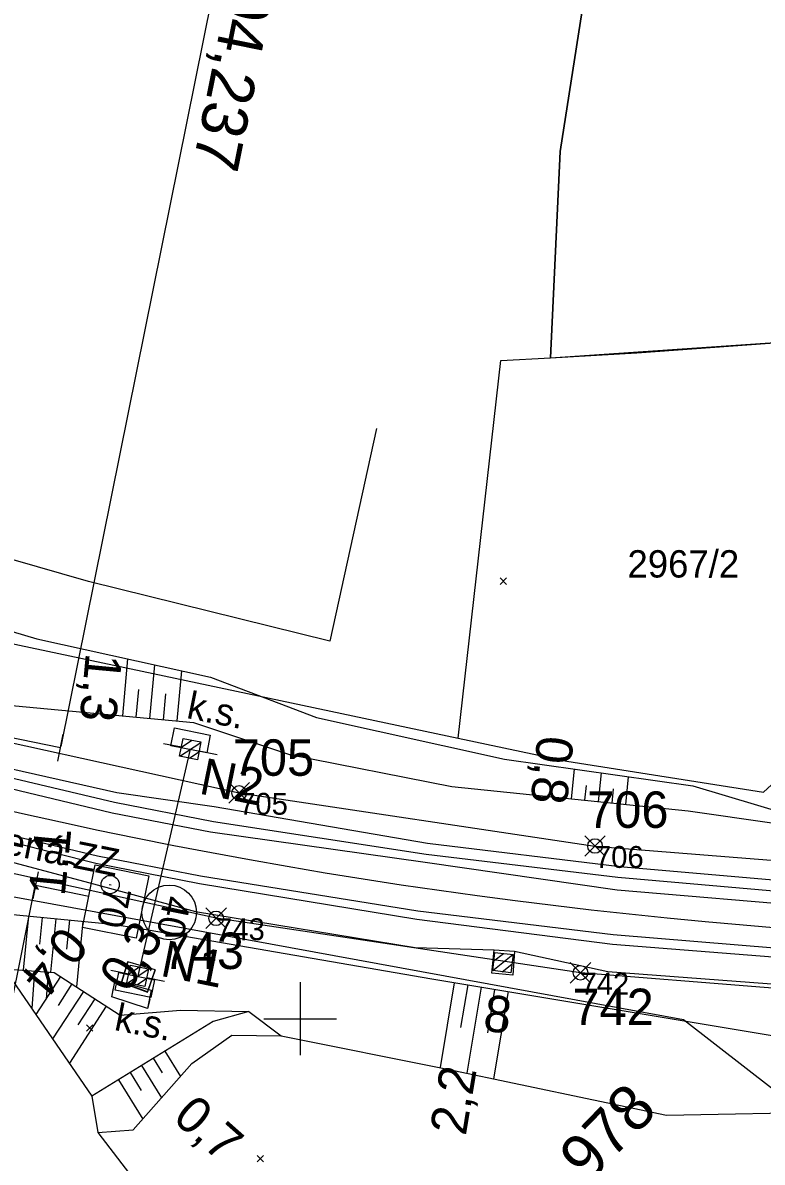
# Model space of a CAD drawing. Extents: x -800194 to -799078, y -1007177 to -1006597.
# Drawn here: x -799715.2 to -799674.6, y -1007007.9 to -1006945.3 of the extents above; entities that cross this region are included whole.
import ezdxf

# ---------------------------------------------------------------- set-up
doc = ezdxf.new("R2010")
doc.units = 0
for name, color, linetype in [('02_Osa_koleje', 7, 'Continuous'), ('Obvod stavby', 7, 'Continuous'), ('Ramove udaje', 7, 'Continuous'), ('Vrstva 11', 7, 'Continuous'), ('Vrstva 12', 7, 'Continuous'), ('Vrstva 17', 7, 'Continuous'), ('Vrstva 2', 7, 'Continuous'), ('Vrstva 23', 7, 'Continuous'), ('Vrstva 25', 7, 'Continuous'), ('Vrstva 4', 7, 'Continuous'), ('Vrstva 48', 7, 'Continuous'), ('Vrstva 49', 7, 'Continuous'), ('Vrstva 5', 7, 'Continuous'), ('Vrstva 50', 7, 'Continuous'), ('Vrstva 53', 7, 'Continuous'), ('Vrstva 55', 7, 'Continuous'), ('Vrstva 57', 7, 'Continuous'), ('Vrstva 60', 7, 'Continuous')]:
    doc.layers.add(name, color=color, linetype=linetype)

msp = doc.modelspace()

# ---------------------------------------------------------------- linework, layer by layer
at = {"layer": '02_Osa_koleje'}
msp.add_arc((-799651.022, -1006703.891), 292, 255.62486, 308.20516, dxfattribs=at)
at = {"layer": 'Obvod stavby'}
for p, q in [((-799703.915, -1006988.172), (-799702.784, -1006987.041)), ((-799703.915, -1006987.041), (-799702.784, -1006988.172)), ((-799684.371, -1006991.088), (-799683.24, -1006989.957)), ((-799684.371, -1006989.957), (-799683.24, -1006991.088)), ((-799705.185, -1006995.056), (-799704.054, -1006993.924)), ((-799705.185, -1006993.924), (-799704.054, -1006995.056)), ((-799685.167, -1006998.043), (-799684.036, -1006996.912)), ((-799685.167, -1006996.912), (-799684.036, -1006998.043))]:
    msp.add_line(p, q, dxfattribs=at)
msp.add_lwpolyline([(-799664.426, -1006999.087), (-799684.601, -1006997.477), (-799704.619, -1006994.49), (-799724.386, -1006990.14), (-799749.554, -1006982.491), (-799772.102, -1006973.528), (-799780.707, -1006969.551), (-799777.674, -1006963.242), (-799769.263, -1006967.129), (-799747.228, -1006975.889), (-799722.648, -1006983.359), (-799703.35, -1006987.606), (-799683.806, -1006990.523), (-799664.228, -1006992.091)], dxfattribs=at)
for centre in [(-799703.35, -1006987.606), (-799683.806, -1006990.523), (-799704.619, -1006994.49), (-799684.601, -1006997.477)]:
    msp.add_circle(centre, 0.4, dxfattribs=at)
at = {"layer": 'Ramove udaje'}
for p, q in [((-799700, -1006998), (-799700, -1007002)), ((-799702, -1007000), (-799700, -1007000)), ((-799700, -1007000), (-799698, -1007000))]:
    msp.add_line(p, q, dxfattribs=at)
at = {"layer": 'Vrstva 11'}
for p, q in [((-799706.526, -1006985.106), (-799707.506, -1006984.907)), ((-799706.602, -1006985.6), (-799705.452, -1006984.836)), ((-799706.525, -1006985.099), (-799705.943, -1006984.713)), ((-799706.036, -1006985.204), (-799708.923, -1006997.646)), ((-799706.082, -1006985.705), (-799705.557, -1006985.356)), ((-799705.546, -1006985.304), (-799704.566, -1006985.501)), ((-799689.419, -1006997.352), (-799688.31, -1006996.481)), ((-799689.355, -1006996.825), (-799688.836, -1006996.418)), ((-799709.413, -1006997.548), (-799710.393, -1006997.349)), ((-799709.489, -1006998.042), (-799708.339, -1006997.278)), ((-799709.412, -1006997.541), (-799708.83, -1006997.155)), ((-799688.896, -1006997.418), (-799688.37, -1006997.005)), ((-799708.969, -1006998.147), (-799708.444, -1006997.798)), ((-799708.433, -1006997.746), (-799707.453, -1006997.943))]:
    msp.add_line(p, q, dxfattribs=at)
for points in [[(-799706.427, -1006984.615), (-799705.447, -1006984.813), (-799705.645, -1006985.793), (-799706.625, -1006985.595)], [(-799689.3, -1006996.362), (-799688.307, -1006996.481), (-799688.426, -1006997.474), (-799689.419, -1006997.355)], [(-799709.314, -1006997.057), (-799708.334, -1006997.255), (-799708.532, -1006998.235), (-799709.512, -1006998.037)]]:
    msp.add_lwpolyline(points, close=True, dxfattribs=at)
at = {"layer": 'Vrstva 12'}
for p, q in [((-799709.809, -1006998.009), (-799709.806, -1006998.009)), ((-799708.388, -1006998.534), (-799708.385, -1006998.533))]:
    msp.add_line(p, q, dxfattribs=at)
for points in [[(-799689.347, -1006996.226), (-799688.222, -1006996.296), (-799688.323, -1006997.618), (-799689.475, -1006997.506), (-799689.347, -1006996.226)], [(-799707.958, -1006997.313), (-799708.385, -1006998.533), (-799709.809, -1006998.009), (-799709.473, -1006996.883)], [(-799707.958, -1006997.313), (-799709.473, -1006996.883), (-799709.806, -1006998.009), (-799708.388, -1006998.534), (-799707.958, -1006997.313)]]:
    msp.add_lwpolyline(points, dxfattribs=at)
at = {"layer": 'Vrstva 17'}
for points in [[(-799695.807, -1006967.611), (-799698.37, -1006979.283), (-799711.621, -1006976.014), (-799725.913, -1006971.918), (-799726.806, -1006975.491)], [(-799708.261, -1006998.95), (-799708.384, -1006999.431), (-799710.346, -1006998.801), (-799710.257, -1006998.331)]]:
    msp.add_lwpolyline(points, dxfattribs=at)
at = {"layer": 'Vrstva 23'}
msp.add_lwpolyline([(-799710.163, -1006997.878), (-799708.18, -1006998.442), (-799708.384, -1006999.431), (-799710.346, -1006998.801), (-799710.163, -1006997.878)], dxfattribs=at)
at = {"layer": 'Vrstva 25'}
for points in [[(-799707.094, -1006985.017), (-799706.896, -1006984.037), (-799704.936, -1006984.433), (-799705.134, -1006985.413), (-799707.094, -1006985.017)], [(-799708.002, -1006997.857), (-799708.2, -1006998.837), (-799710.16, -1006998.441), (-799709.962, -1006997.461), (-799708.002, -1006997.857)]]:
    msp.add_lwpolyline(points, dxfattribs=at)
at = {"layer": 'Vrstva 4'}
for points in [[(-799766.319, -1006970.565), (-799760.949, -1006972.542), (-799747.638, -1006977.46), (-799730.549, -1006982.982), (-799710.066, -1006987.578), (-799704.728, -1006988.346), (-799693.001, -1006990.373), (-799682.434, -1006991.64), (-799671.27, -1006992.619), (-799659.31, -1006993.026), (-799648.69, -1006993.125), (-799637.398, -1006992.704), (-799625.913, -1006992.175), (-799614.965, -1006990.831), (-799603.911, -1006989.312), (-799592.728, -1006987.172), (-799581.605, -1006984.547), (-799570.583, -1006981.598), (-799559.909, -1006978.216), (-799542.956, -1006972.25), (-799531.79, -1006967.658), (-799521.285, -1006962.191), (-799511.236, -1006957.129)], [(-799779.678, -1006964.304), (-799766.319, -1006970.565), (-799761.253, -1006973.176), (-799747.77, -1006978.421), (-799730.774, -1006983.8), (-799710.333, -1006988.709), (-799704.916, -1006989.741), (-799693.131, -1006991.407), (-799682.585, -1006992.929), (-799671.325, -1006993.879), (-799659.363, -1006994.45), (-799648.66, -1006994.501), (-799637.23, -1006994.127), (-799626.066, -1006993.335), (-799614.788, -1006992.17), (-799603.669, -1006990.506), (-799592.467, -1006988.452), (-799581.281, -1006985.916), (-799570.22, -1006982.998), (-799559.296, -1006979.606), (-799542.375, -1006973.485), (-799531.236, -1006968.774), (-799520.48, -1006963.762), (-799510.394, -1006958.536)], [(-799776.864, -1006969.085), (-799770.965, -1006971.646), (-799761.91, -1006975.649), (-799748.544, -1006980.777), (-799731.457, -1006986.215), (-799711.132, -1006991.054), (-799705.482, -1006992.16), (-799693.53, -1006994.084), (-799682.801, -1006995.384), (-799671.514, -1006996.319), (-799659.449, -1006996.851), (-799648.588, -1006996.949), (-799637.262, -1006996.573), (-799625.835, -1006995.773), (-799614.546, -1006994.586), (-799603.199, -1006992.945), (-799591.969, -1006990.857), (-799580.647, -1006988.335), (-799569.534, -1006985.311), (-799558.557, -1006981.947), (-799541.405, -1006975.739), (-799530.263, -1006971.071), (-799519.455, -1006966), (-799509.248, -1006960.724)], [(-799776.864, -1006969.085), (-799771.262, -1006971.982), (-799762.131, -1006976.093), (-799748.706, -1006981.286), (-799731.51, -1006986.353), (-799711.222, -1006991.459), (-799705.527, -1006992.587), (-799693.582, -1006994.543), (-799682.85, -1006995.904), (-799671.5, -1006996.805), (-799659.556, -1006997.356), (-799648.616, -1006997.341), (-799637.276, -1006997.071), (-799625.828, -1006996.297), (-799614.43, -1006995.109), (-799603.18, -1006993.475), (-799591.849, -1006991.264), (-799580.564, -1006988.698), (-799569.449, -1006985.746), (-799558.385, -1006982.386), (-799541.268, -1006976.227), (-799530.102, -1006971.505), (-799519.398, -1006966.36), (-799509.087, -1006961.127)], [(-799779.011, -1006963.023), (-799770.632, -1006967.944), (-799766.319, -1006970.565), (-799761.021, -1006972.82), (-799747.748, -1006977.966), (-799730.719, -1006983.271), (-799710.195, -1006988.108), (-799704.765, -1006989.181), (-799693.072, -1006990.965), (-799682.554, -1006992.238), (-799671.266, -1006993.222), (-799659.388, -1006993.765), (-799648.658, -1006993.824), (-799637.385, -1006993.531), (-799625.769, -1006992.728), (-799614.9, -1006991.542), (-799603.91, -1006989.963), (-799592.572, -1006987.892), (-799581.421, -1006985.419), (-799570.327, -1006982.332), (-799559.429, -1006979.066), (-799542.601, -1006973.013), (-799531.454, -1006968.25), (-799520.744, -1006963.214)], [(-799776.864, -1006969.085), (-799771.693, -1006972.522), (-799762.217, -1006976.394), (-799748.898, -1006981.647), (-799733.68, -1006986.66), (-799728.795, -1006987.945), (-799711.349, -1006992.599), (-799705.744, -1006994.116), (-799693.689, -1006996.09), (-799689.347, -1006996.226), (-799688.222, -1006996.296), (-799683.105, -1006997.407), (-799671.667, -1006998.275)]]:
    msp.add_lwpolyline(points, dxfattribs=at)
at = {"layer": 'Vrstva 48'}
for p, q in [((-799709.746, -1006983.382), (-799709.457, -1006980.257)), ((-799708.252, -1006983.521), (-799707.98, -1006980.58)), ((-799706.759, -1006983.659), (-799706.504, -1006980.903)), ((-799708.999, -1006983.452), (-799708.859, -1006981.935)), ((-799707.506, -1006983.59), (-799707.374, -1006982.166)), ((-799685.1, -1006987.935), (-799684.931, -1006986.304)), ((-799683.608, -1006988.09), (-799683.444, -1006986.513)), ((-799682.116, -1006988.245), (-799681.958, -1006986.722)), ((-799684.354, -1006988.013), (-799684.271, -1006987.211)), ((-799682.862, -1006988.168), (-799682.782, -1006987.393)), ((-799714.916, -1006994.364), (-799715.209, -1006997.336)), ((-799714.169, -1006994.437), (-799714.315, -1006995.913)), ((-799713.423, -1006994.511), (-799713.712, -1006997.443)), ((-799712.677, -1006994.585), (-799712.835, -1006996.19)), ((-799711.93, -1006994.658), (-799712.285, -1006998.256)), ((-799714.594, -1006997.38), (-799714.742, -1006999.446)), ((-799713.846, -1006997.433), (-799713.954, -1006998.934)), ((-799713.165, -1006997.685), (-799714.519, -1006999.77)), ((-799712.536, -1006998.093), (-799713.297, -1006999.266)), ((-799691.538, -1006998.023), (-799692.31, -1007002.68)), ((-799690.798, -1006998.146), (-799691.187, -1007000.488)), ((-799711.907, -1006998.502), (-799713.599, -1007001.107)), ((-799690.058, -1006998.269), (-799690.841, -1007002.985)), ((-799689.318, -1006998.392), (-799689.712, -1007000.766)), ((-799688.579, -1006998.514), (-799689.372, -1007003.296)), ((-799710.649, -1006999.319), (-799712.678, -1007002.443)), ((-799711.278, -1006998.911), (-799712.208, -1007000.343)), ((-799707.427, -1007001.776), (-799706.571, -1007003.169)), ((-799708.066, -1007002.169), (-799707.578, -1007002.963)), ((-799709.344, -1007002.954), (-799708.736, -1007003.943)), ((-799708.705, -1007002.561), (-799707.609, -1007004.344)), ((-799709.983, -1007003.347), (-799708.648, -1007005.518))]:
    msp.add_line(p, q, dxfattribs=at)
at = {"layer": 'Vrstva 49'}
for p, q in [((-799689.011, -1006975.814), (-799688.657, -1006976.168)), ((-799689.011, -1006976.168), (-799688.657, -1006975.814)), ((-799711.736, -1007000.327), (-799711.382, -1007000.681)), ((-799711.736, -1007000.681), (-799711.382, -1007000.327)), ((-799702.358, -1007007.501), (-799702.004, -1007007.855)), ((-799702.358, -1007007.855), (-799702.004, -1007007.501))]:
    msp.add_line(p, q, dxfattribs=at)
for points in [[(-799710.319, -1006994.817), (-799708.871, -1006995.032), (-799692.771, -1006997.819), (-799673.296, -1007001.049), (-799659.562, -1007000.479), (-799648.457, -1007000.689), (-799625.451, -1006999.097), (-799615.697, -1006997.513), (-799614.57, -1006997.347), (-799602.963, -1006995.575), (-799579.498, -1006991.091), (-799558.66, -1006984.762), (-799544.861, -1006980.115), (-799538.187, -1006977.215), (-799529.217, -1006973.339), (-799517.856, -1006968.167), (-799516.556, -1006966.997), (-799515.527, -1006966.511), (-799507.817, -1006962.779)], [(-799728.174, -1006980.607), (-799726.806, -1006975.491), (-799714.47, -1006979.159), (-799704.928, -1006981.248), (-799699.097, -1006983.466), (-799688.779, -1006985.763), (-799678.423, -1006987.219), (-799669.363, -1006989.921)], [(-799728.174, -1006980.607), (-799715.637, -1006982.837), (-799705.851, -1006983.743), (-799700.586, -1006985.508), (-799691.67, -1006987.253), (-799678.693, -1006988.601), (-799669.363, -1006989.921)], [(-799733.039, -1007005.939), (-799736.26, -1007003.86), (-799742.34, -1006997.896), (-799743.342, -1006994.901), (-799739.871, -1006991.182), (-799734.968, -1006991.052), (-799728.642, -1006990.92), (-799723.01, -1006991.966), (-799716.141, -1006994.243), (-799710.319, -1006994.817)], [(-799716.248, -1006997.261), (-799711.439, -1007004.242), (-799711.113, -1007006.25), (-799707.442, -1007011.019), (-799702.585, -1007019.595), (-799698.243, -1007027.001), (-799684.872, -1007037.347), (-799668.902, -1007051.666)], [(-799716.248, -1006997.261), (-799713.515, -1006997.457), (-799709.895, -1006999.809), (-799706.577, -1006999.538), (-799702.816, -1006999.606), (-799701.051, -1007000.939), (-799691.907, -1007002.76), (-799679.882, -1007005.3), (-799670.416, -1007005.115), (-799649.119, -1007006.099), (-799641.812, -1007006.94)], [(-799702.816, -1006999.606), (-799704.779, -1007000.148), (-799711.439, -1007004.242)], [(-799711.113, -1007006.25), (-799709.167, -1007006.105), (-799705.943, -1007002.46), (-799703.761, -1007000.905), (-799701.051, -1007000.939)]]:
    msp.add_lwpolyline(points, dxfattribs=at)
at = {"layer": 'Vrstva 5'}
for p, q in [((-799703.26, -1006936.046), (-799713.152, -1006985.058)), ((-799713.314, -1006985.864), (-799713.018, -1006984.394)), ((-799713.166, -1006985.129), (-799716.107, -1006984.535)), ((-799714.395, -1006991.944), (-799714.691, -1006993.414)), ((-799720.48, -1007022.094), (-799714.568, -1006992.803)), ((-799714.543, -1006992.679), (-799711.602, -1006993.273))]:
    msp.add_line(p, q, dxfattribs=at)
msp.add_lwpolyline([(-799711.949, -1006994.988), (-799711.256, -1006991.557), (-799708.315, -1006992.151), (-799709.008, -1006995.581)], close=True, dxfattribs=at)
msp.add_circle((-799707.191, -1006994.163), 1.5, dxfattribs=at)
at = {"layer": 'Vrstva 50'}
msp.add_line((-799710.486, -1006992.629), (-799710.388, -1006992.649), dxfattribs=at)
msp.add_circle((-799710.437, -1006992.639), 0.5, dxfattribs=at)
at = {"layer": 'Vrstva 53'}
msp.add_lwpolyline([(-799679.26, -1006911.01), (-799685.71, -1006952.41), (-799686.25, -1006963.73), (-799670.17, -1006962.64)], dxfattribs=at)
at = {"layer": 'Vrstva 55'}
msp.add_line((-799727.37, -1006976.97), (-799691.32, -1006984.61), dxfattribs=at)
for points in [[(-799686.25, -1006963.73), (-799685.71, -1006952.41), (-799679.26, -1006911.01)], [(-799686.25, -1006963.73), (-799681.51, -1006963.46), (-799670.17, -1006962.64), (-799668.03, -1006961.74)], [(-799691.32, -1006984.61), (-799688.98, -1006963.88), (-799686.25, -1006963.73)], [(-799691.32, -1006984.61), (-799685.35, -1006985.87), (-799674.55, -1006987.57), (-799667.43, -1006981.06)], [(-799667.22, -1007009.16), (-799678.94, -1007000.07), (-799720.83, -1006992.39), (-799728.88, -1006993.59), (-799733.28, -1006992.13)]]:
    msp.add_lwpolyline(points, dxfattribs=at)
at = {"layer": 'Vrstva 60'}
for p, q in [((-799703.35, -1006987.606), (-799703.35, -1006987.606)), ((-799683.806, -1006990.523), (-799683.806, -1006990.523)), ((-799704.619, -1006994.49), (-799704.619, -1006994.49)), ((-799684.601, -1006997.477), (-799684.601, -1006997.477))]:
    msp.add_line(p, q, dxfattribs=at)

# ---------------------------------------------------------------- texts
at = {"layer": 'Obvod stavby'}
for s, p in [('705', (-799703.699, -1006986.669)), ('706', (-799684.231, -1006989.528)), ('743', (-799707.547, -1006997.273)), ('742', (-799685.04, -1007000.35))]:
    msp.add_text(s, height=2, rotation=360, dxfattribs=at).set_placement(p)
at = {"layer": 'Vrstva 11'}
for s, rotation, p in [('N2', 348.58947, (-799705.617, -1006987.633)), ('N1', 348.58947, (-799707.745, -1006997.634)), ('8', 353.12702, (-799690.001, -1007000.65))]:
    msp.add_text(s, height=2, rotation=rotation, dxfattribs=at).set_placement(p)
at = {"layer": 'Vrstva 2'}
msp.add_text('evid. km 101,978', height=2.5, rotation=45.83096, dxfattribs=at).set_placement((-799698.03, -1007023.349))
at = {"layer": 'Vrstva 25'}
for p in [(-799706.29, -1006983.492), (-799710.262, -1007000.61)]:
    msp.add_text('k.s.', height=1.5, rotation=348.58947, dxfattribs=at).set_placement(p)
at = {"layer": 'Vrstva 48'}
for s, rotation, p in [('1,3', 264.71056, (-799711.765, -1006979.895)), ('0,8', 264.06961, (-799686.958, -1006984.411)), ('1,1', 84.36932, (-799712.931, -1006993.316)), ('0,3', 56.98726, (-799709.468, -1006998.657)), ('0,4', 230.6701, (-799713.067, -1006994.798)), ('2,2', 80.58301, (-799690.907, -1007006.463)), ('0,7', 318.50726, (-799707.069, -1007005.538))]:
    msp.add_text(s, height=2, rotation=rotation, dxfattribs=at).set_placement(p)
at = {"layer": 'Vrstva 5'}
for s, height, p in [('km 204,237', 2.5, (-799702.455, -1006936.038)), ('70', 1.5, (-799710.735, -1006992.65)), ('40', 1.5, (-799707.452, -1006993.178))]:
    msp.add_text(s, height=height, rotation=258.58947, dxfattribs=at).set_placement(p)
at = {"layer": 'Vrstva 50'}
msp.add_text('zničená ZZ', height=1.5, rotation=348.58947, dxfattribs=at).set_placement((-799719.846, -1006990.228))
at = {"layer": 'Vrstva 57'}
msp.add_text('2967/2', height=1.5, dxfattribs=at).set_placement((-799682.02, -1006975.79))
at = {"layer": 'Vrstva 60'}
for s, p in [('705', (-799703.35, -1006988.806)), ('706', (-799683.806, -1006991.723)), ('743', (-799704.619, -1006995.69)), ('742', (-799684.601, -1006998.677))]:
    msp.add_text(s, height=1.2, dxfattribs=at).set_placement(p)

doc.saveas('drawing.dxf')
